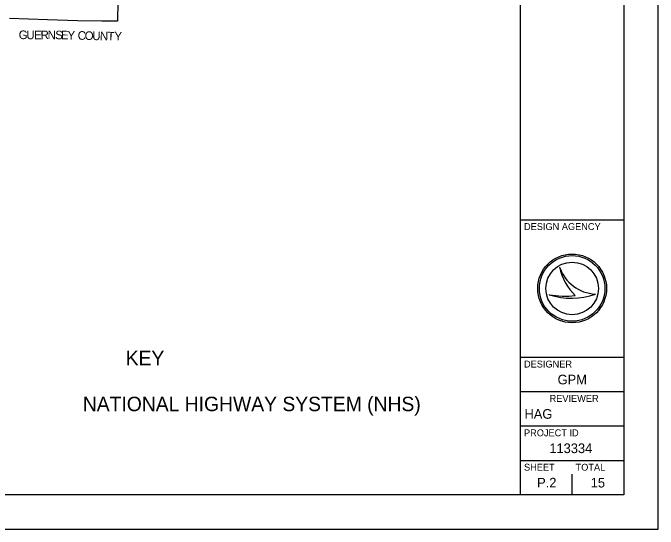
# Model space of a CAD drawing. Extents: x 1913970 to 2276415, y 78841 to 927181.
# Drawn here: x 2201350 to 2276415, y 751181 to 811241 of the extents above; entities that cross this region are included whole.
import ezdxf

# ---------------------------------------------------------------- set-up
doc = ezdxf.new("R2010")
doc.units = 0
for name, color, linetype in [('Default', 7, 'Continuous'), ('GM_X_County', 7, 'Continuous'), ('GM_X_County_Text', 7, 'Continuous'), ('SH_Border', 7, 'Continuous'), ('SH_Cut_Line', 7, 'Continuous'), ('SH_Data', 7, 'Continuous')]:
    doc.layers.add(name, color=color, linetype=linetype)

msp = doc.modelspace()

# ---------------------------------------------------------------- linework, layer by layer
at = {"layer": 'GM_X_County'}
msp.add_lwpolyline([(2213626, 817104), (2213518, 810296), (2211703, 810263), (2208876, 810317), (2205381, 810448), (2200936, 810586)], dxfattribs=at)
at = {"layer": 'SH_Border'}
for p, q in [((2260415, 755181), (2260415, 923181)), ((2260415, 787181), (2272415, 787181)), ((2260415, 771181), (2272415, 771181)), ((2260415, 767181), (2272415, 767181)), ((2260415, 763181), (2272415, 763181)), ((2260415, 759181), (2272415, 759181))]:
    msp.add_line(p, q, dxfattribs=at)
msp.add_lwpolyline([(2016415, 923181), (2272415, 923181), (2272415, 755181), (2016415, 755181)], close=True, dxfattribs=at)
at = {"layer": 'SH_Cut_Line'}
msp.add_lwpolyline([(2004415, 751181), (2276415, 751181), (2276415, 927181), (2004415, 927181)], close=True, dxfattribs=at)
at = {"layer": 'SH_Data'}
for p, q in [((2264955, 781657), (2264955, 781657)), ((2266415, 779181), (2266415, 779181)), ((2263753, 778457), (2263753, 778457)), ((2269114, 778529), (2269114, 778529)), ((2266415, 755181), (2266415, 757581)), ((2263415, 756581), (2263415, 756581))]:
    msp.add_line(p, q, dxfattribs=at)
for radius in [4000, 3814, 3814, 3058]:
    msp.add_circle((2266415, 779181), radius, dxfattribs=at)
for centre, radius, start, end in [((2269343, 783162), 4639, 198.92567, 198.93195), ((2271189, 782941), 6365, 191.63793, 191.64215), ((2269343, 783162), 4639, 198.93195, 267.16574), ((2271189, 782941), 6365, 191.64215, 226.09467), ((2266331, 786141), 8105, 251.45764, 290.08324), ((2265599, 788415), 10128, 259.49639, 259.49952), ((2266331, 786141), 8105, 251.45274, 251.45764), ((2265599, 788415), 10128, 259.49952, 276.66723)]:
    msp.add_arc(centre, radius, start, end, dxfattribs=at)

# ---------------------------------------------------------------- texts
at = {"layer": 'Default'}
for s, p in [('KEY', (2214470, 770248)), ('NATIONAL HIGHWAY SYSTEM (NHS)', (2209485, 764901))]:
    msp.add_text(s, height=1680, dxfattribs=at).set_placement(p)
at = {"layer": 'GM_X_County_Text'}
for s, rotation, p in [('G', 358.82009, (2202018, 808203)), ('U', 359.18847, (2202909, 808184)), ('E', 0.18794, (2203812, 808172)), ('R', 0.94165, (2204575, 808174)), ('N', 359.48566, (2205382, 808188)), ('S', 359.0235, (2206264, 808180)), ('E', 358.77079, (2206940, 808168)), ('Y', 358.68305, (2207688, 808152)), ('C', 358.66131, (2208875, 808125)), ('O', 358.66021, (2209689, 808106)), ('U', 358.66128, (2210573, 808085)), ('N', 358.66021, (2211458, 808064)), ('T', 358.66029, (2212342, 808044)), ('Y', 358.66029, (2213143, 808044))]:
    msp.add_text(s, height=1000, rotation=rotation, dxfattribs=at).set_placement(p)
at = {"layer": 'SH_Data'}
for s, height, p in [('DESIGN AGENCY', 800, (2260815, 785981)), ('DESIGNER', 800, (2260815, 769981)), ('GPM', 1120, (2264722, 768021)), ('REVIEWER', 800, (2263790, 765981)), ('HAG', 1120, (2260869, 764021)), ('PROJECT ID', 800, (2260815, 761981)), ('113334', 1120, (2263759, 760021)), ('SHEET', 800, (2260815, 757981)), ('TOTAL', 800, (2266815, 757981)), ('P.2', 1120, (2262339, 756021)), ('15', 1120, (2268573, 756021))]:
    msp.add_text(s, height=height, dxfattribs=at).set_placement(p)

doc.saveas('drawing.dxf')
